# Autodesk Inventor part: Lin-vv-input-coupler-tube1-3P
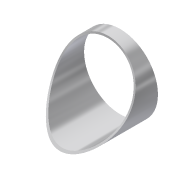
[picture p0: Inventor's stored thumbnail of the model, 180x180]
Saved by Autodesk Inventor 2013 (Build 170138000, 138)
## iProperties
Created: 2012-05
Part Number: Lin-vv-input-coupler-tube1-3P
Material: Stainless Steel, 316
Description: INPUT COUPLER TUBE
Document SubType Name: Modeling
Designer: Henneborn
Manufacturer: Standard
Standards Organization: Custom
Density: 7.9 g/cm^3
Mass: 4160.04 g
Surface Area: 1740.09 cm^2
Volume: 526.587 cm^3
Rohmasse: 10,75" O.D. x 0,25 WALL x 7,3"
Author: vm
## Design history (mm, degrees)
sketch "Sketch1"
  geometry: C1 r 136.525 at (0, 0); C2 r 130.175 at (0, 0); 1 further point
  constraints: 2 centre point, 1 coincident
  dimensions: "d0" = 136.525 radius of C1; "d1" = 130.175 radius of C2
extrude "Extrusion1" new body sketch "Sketch1" stored distance "d2" = 279.4; taper "d3" = 0 deg
sketch "Sketch4"
  geometry: L1 (0, -333.375)-(0, 1044.575) reference; L2 (130.175, -139.7)-(-130.175, -139.7) reference; C1 r 476.25 at (241.3, 367.665)
  constraints: 1 centre point
  dimensions: "d10" = 476.25 radius of C1; "d12" = 241.3 distance from line of L1 C1.centre; "d16" = 507.365 distance from line of C1.centre L2
extrude "Extrusion4" cut sketch "Sketch4" stored distance "d13" = 3.81; taper "d14" = 0 deg
body "Solid1"
